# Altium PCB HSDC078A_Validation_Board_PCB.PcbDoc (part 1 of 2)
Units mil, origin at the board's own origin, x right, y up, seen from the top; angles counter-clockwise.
Board outline 3100 x 3100 mil, 4 copper layers (L1-TOP, L2, L3, L4-BOT), stack 61.6 mil thick; 80 components, 31 nets, 179 pads, 275 vias.
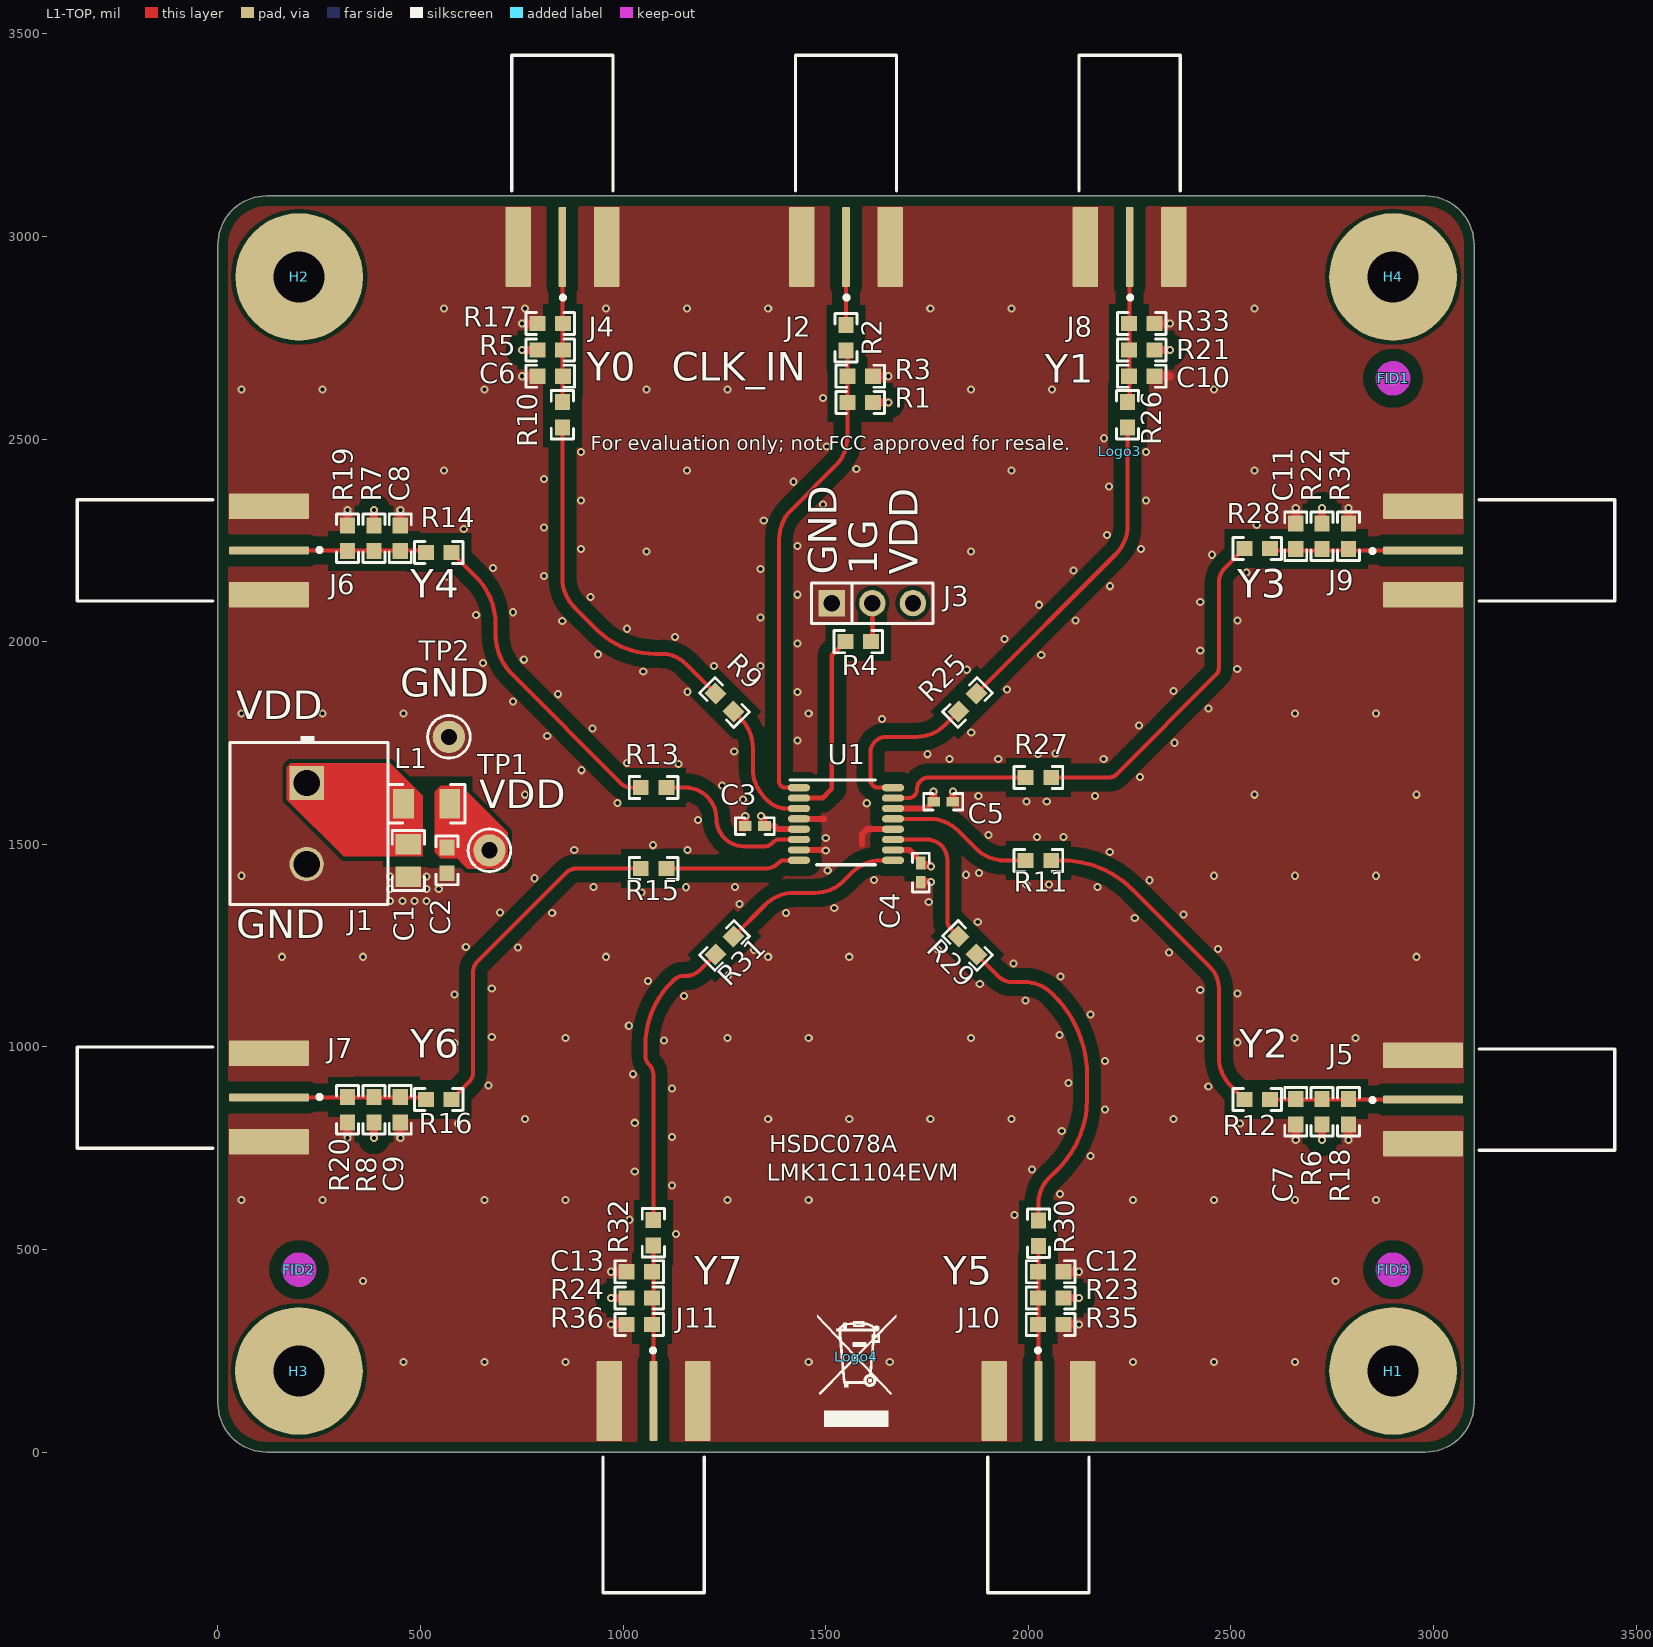
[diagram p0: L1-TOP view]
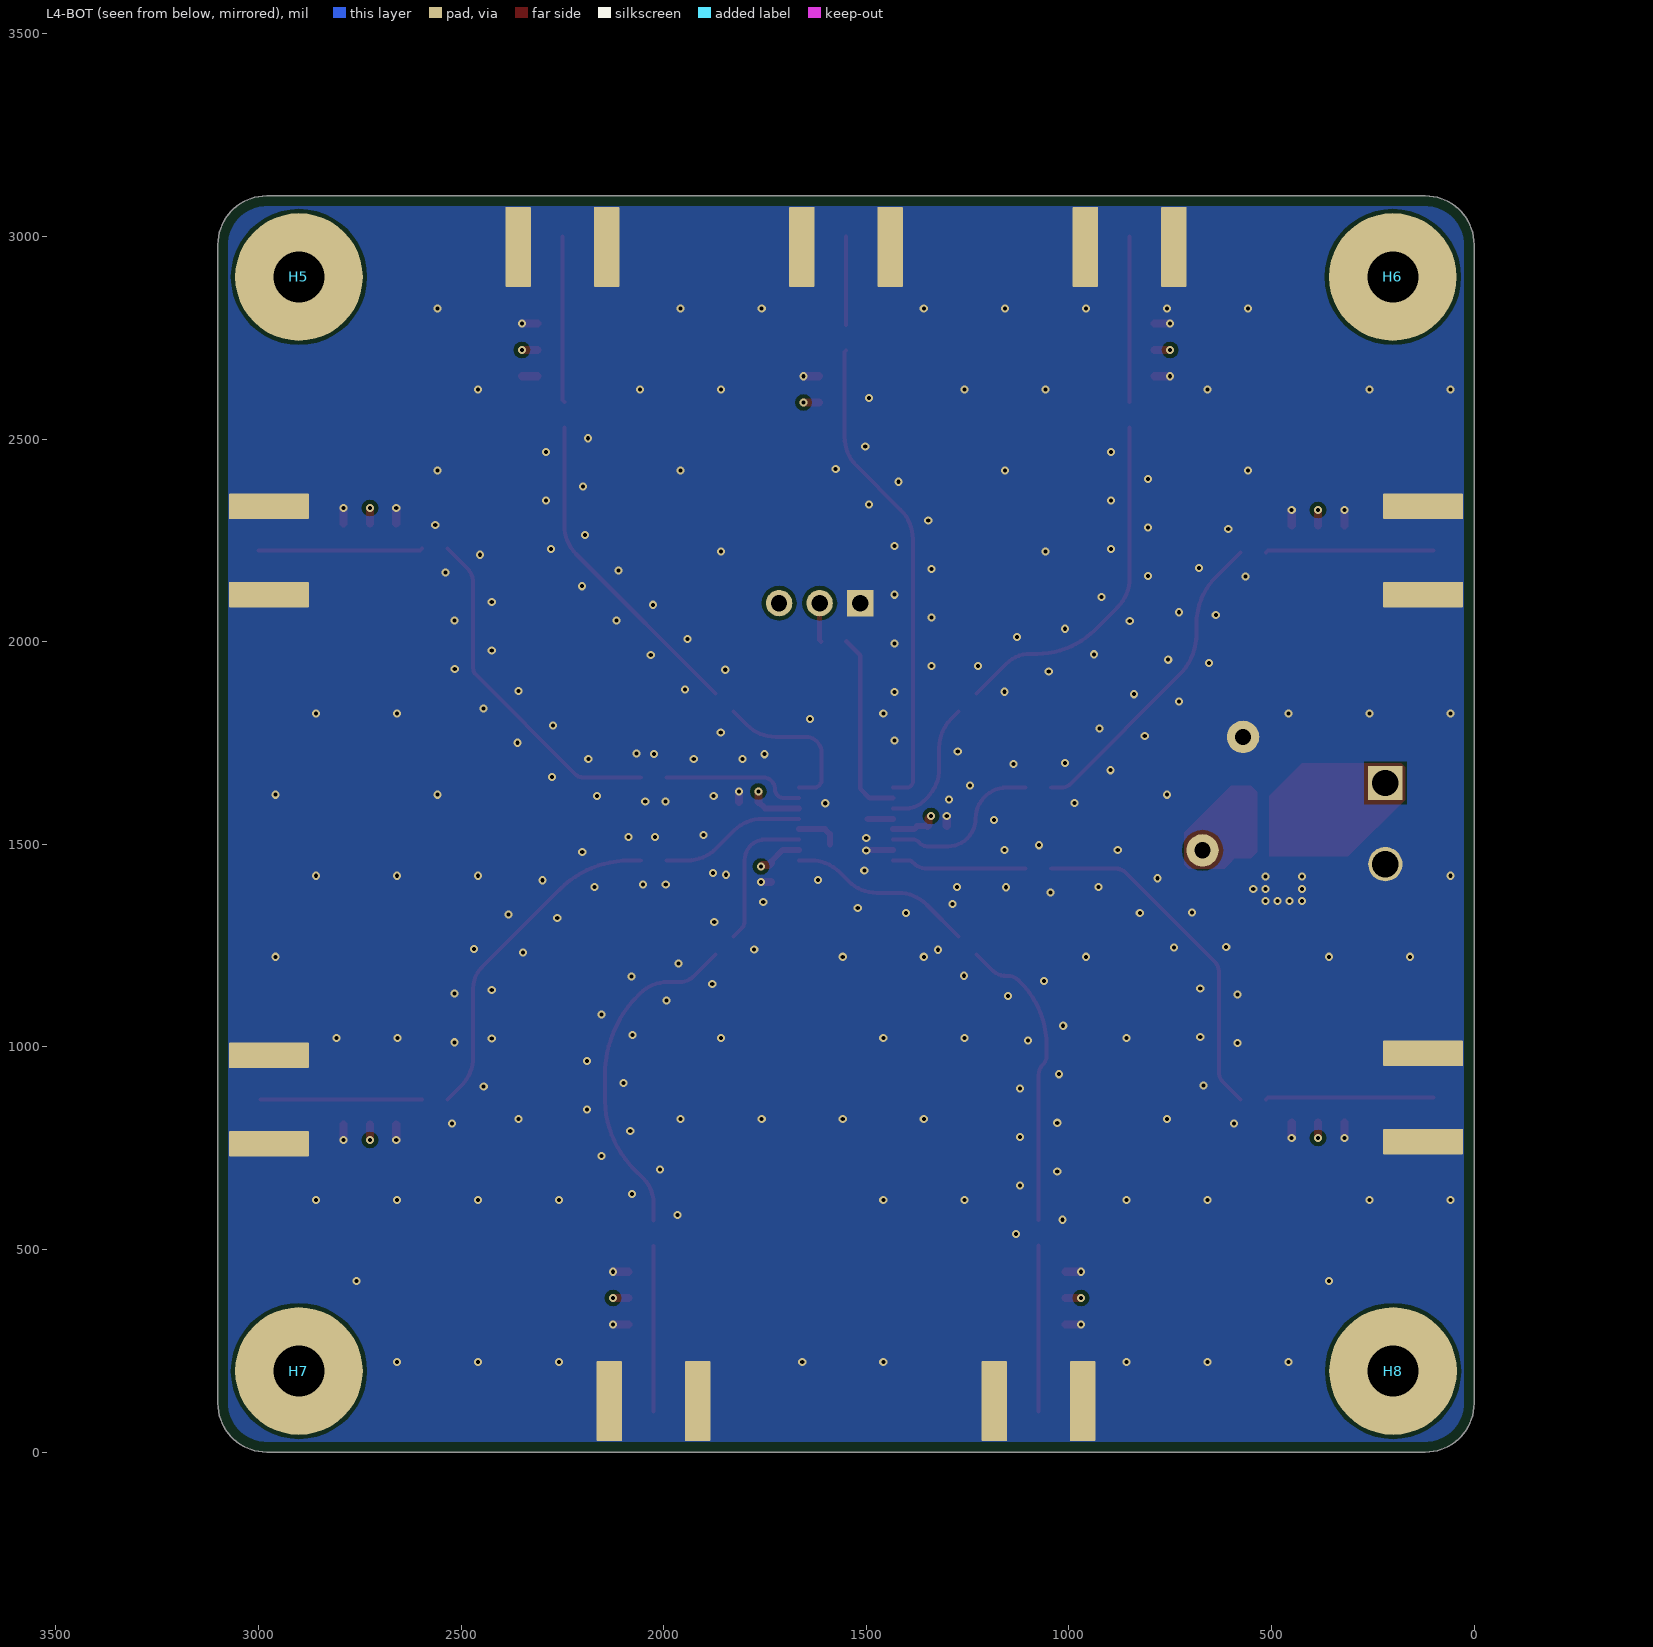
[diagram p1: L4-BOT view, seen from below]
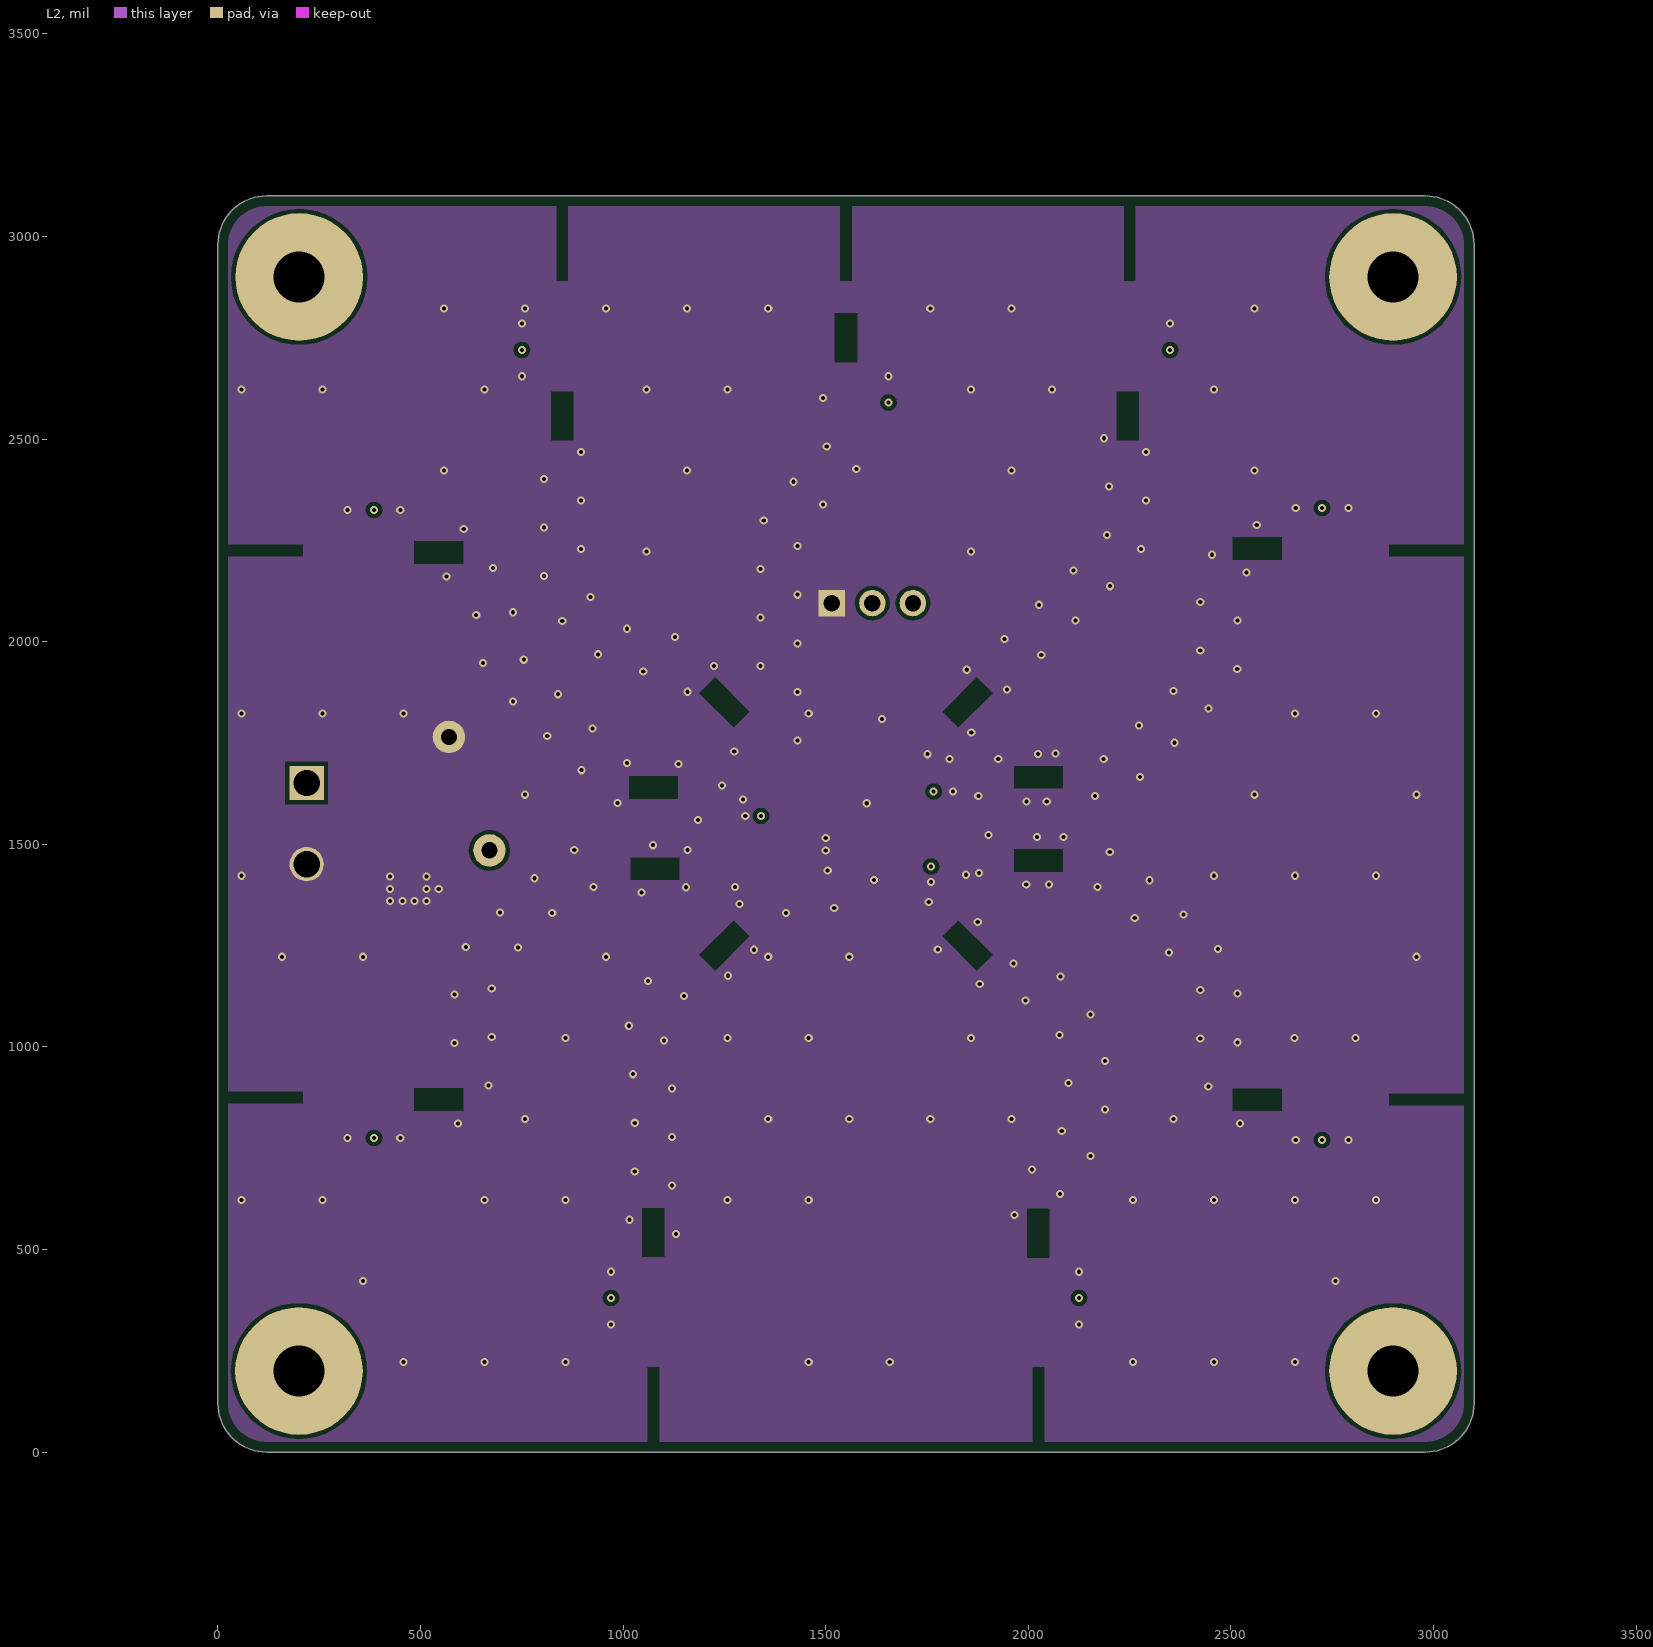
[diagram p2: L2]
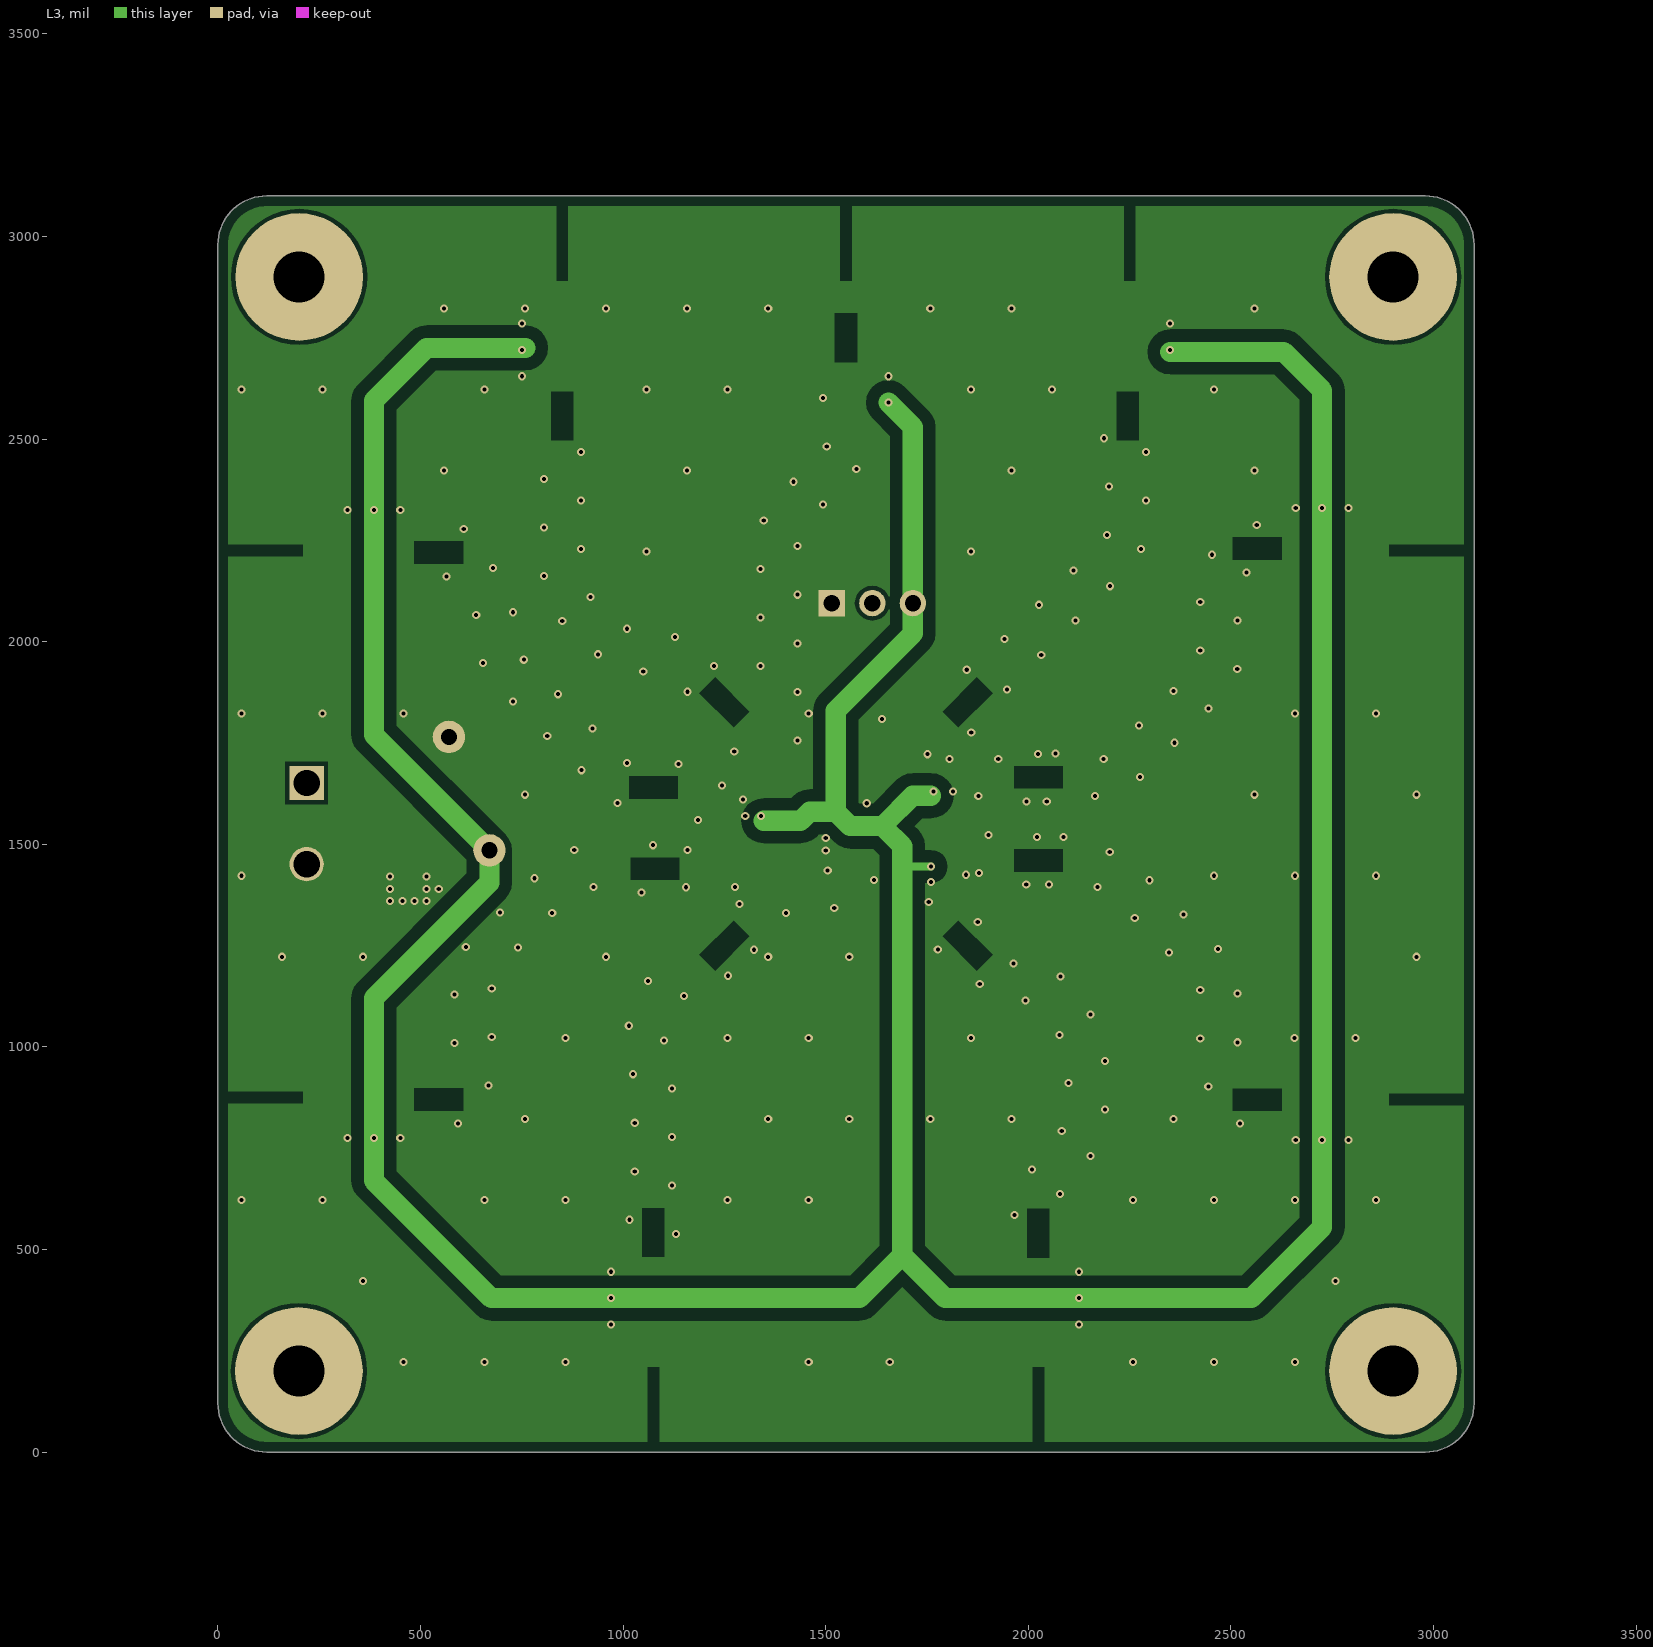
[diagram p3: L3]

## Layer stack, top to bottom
Top Solder: solder mask 0.4, Solder Resist, Dk 3.5
L1-TOP: signal copper 1.4
Dielectric 1: prepreg 6, FR-4 High TG, Dk 4.2
L2: signal copper 1.4
Dielectric 2: core 44, FR-4 High TG, Dk 4.2
L3: signal copper 1.4
Dielectric 3: prepreg 6, FR-4 High TG, Dk 4.2
L4-BOT: signal copper 1.4
Bottom Solder: solder mask 0.4, Solder Resist, Dk 3.5

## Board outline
120,0 cw(c120,120) 0,120 0,2980 cw(c120,2980) 120,3100 2980,3100 cw(c2980,2980) 3100,2980 3100,120 cw(c2980,120) 2980,0

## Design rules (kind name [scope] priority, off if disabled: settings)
AcuteAngle [All] p1: minimum=4.50000000000000E+0001 checktracksonly=FALSE
AssemblyTestPointUsage [All] p1: valid=2
BoardOutlineClearance BoardOutlineClearance_MountingHoles [OnCopper and InComponentClass('Mounting Holes')] p1: gap=39.37 ignorepadtopadclearanceinfootprint=FALSE
BoardOutlineClearance BoardOutlineClearance_Poly [OnCopper and IsPoly] p2: gap=25 ignorepadtopadclearanceinfootprint=FALSE
BoardOutlineClearance [OnCopper and Not InComponentClass('Logo') and not InComponentClass('FiducialMark') and not InRegion(1000,500,4000,800) and not InPoly] p3: gap=-1 ignorepadtopadclearanceinfootprint=FALSE
Clearance Clearance_Poly [InPolygon] p1: gap=10 ignorepadtopadclearanceinfootprint=TRUE except(30: Arc-Poly Track-Poly SMDPad-Poly)
Clearance Clearance_Keepouts [((IsTrack Or IsArc) And Not InPoly) And IsFree and IsKeepOut vs ((IsTrack Or IsArc) And Not InPoly) And IsFree and IsKeepOut] p2: gap=0 ignorepadtopadclearanceinfootprint=FALSE
Clearance Clearance_FiducialMark [IsKeepOut and InComponentClass('FiducialMark') vs IsPad and InComponentClass('FiducialMark')] p3: gap=0 ignorepadtopadclearanceinfootprint=FALSE
Clearance [All] p4: gap=7.87 ignorepadtopadclearanceinfootprint=TRUE
ComponentClearance ComponentClearance_MountingHoles_FiducialMarks [InComponentClass('Mounting Holes') vs InComponentClass('FiducialMark')] p1: gap=50 collisioncheckmode=3 verticalgap=10 showdistances=FALSE
ComponentClearance ComponentClearance_Shunt [InComponentClass('Header') vs InComponentClass('Shunt')] p2: gap=0 collisioncheckmode=3 verticalgap=0 showdistances=FALSE
ComponentClearance ComponentClearance_Logo [InComponentClass('Logo')] p3: gap=50 collisioncheckmode=3 verticalgap=10 showdistances=FALSE
ComponentClearance ComponentClearance_ScrewToNut [(HasFootprint('NY PMS 440 0025 PH')) vs (HasFootprint('Keystone_1902C'))] p4: gap=5 collisioncheckmode=3 verticalgap=10 showdistances=FALSE
ComponentClearance ComponentClearance_MountingHoles [InComponentClass('Mounting Holes')] p5: gap=100 collisioncheckmode=3 verticalgap=100000 showdistances=FALSE
ComponentClearance ComponentClearance_SmallPassives [HasFootprint('0201*') or HasFootprint('0402*') or HasFootprint('0508') or HasFootprint('0603*') or HasFootprint('0612') or HasFootprint('0805*') or HasFootprint('0815*') or HasFootprint('0830*') or HasFootprint('1206*') or HasFootprint('1210*') or HasFootprint('1808*') or HasFootprint('1812*') or HasFootprint('1825*') or HasFootprint('2010*') or HasFootprint('2220*') or HasFootprint('2225*') or HasFootprint('2512*') or HasFootprint('2728*') or HasFootprint('3518*') vs HasFootprint('0201*') or HasFootprint('0402*') or HasFootprint('0508') or HasFootprint('0603*') or HasFootprint('0612') or HasFootprint('0805*') or HasFootprint('0815*') or HasFootprint('0830*') or HasFootprint('1206*') or HasFootprint('1210*') or HasFootprint('1808*') or HasFootprint('1812*') or HasFootprint('1825*') or HasFootprint('2010*') or HasFootprint('2220*') or HasFootprint('2225*') or HasFootprint('2512*') or HasFootprint('2728*') or HasFootprint('3518*')] p6: gap=14.96 collisioncheckmode=3 verticalgap=10 showdistances=FALSE
ComponentClearance ComponentClearance_THtoSMT [IsThruComponent vs IsSMTComponent] p7: gap=20 collisioncheckmode=3 verticalgap=30 showdistances=FALSE
ComponentClearance ComponentClearance_THtoTH [IsThruComponent vs IsThruComponent] p8: gap=30 collisioncheckmode=3 verticalgap=30 showdistances=FALSE
ComponentClearance [All] p9: gap=30 collisioncheckmode=3 verticalgap=10 showdistances=FALSE
DiffPairsRouting [All] p1: maxlimit=100 minlimit=10 mostfreqgap=10 toplayer_minwidth=15 toplayer_maxwidth=15 toplayer_prefwidth=15 midlayer1_minwidth=15 midlayer1_maxwidth=15 midlayer1_prefwidth=15 midlayer2_minwidth=15 midlayer2_maxwidth=15 midlayer2_prefwidth=15 bottomlayer_minwidth=15 bottomlayer_maxwidth=15 bottomlayer_prefwidth=15 maxuncoupledlength=1000
FabricationTestPointUsage TestPointUsage [All] p1: valid=2 allowmultiple=FALSE
FabricationTestpoint Testpoint [All] p1: side=3 testpointundercomponent=TRUE minsize=40 maxsize=100 preferedsize=60 minholesize=0 maxholesize=40 preferedholesize=32 testpointgrid=1 allowsidetop=TRUE allowsidebottom=TRUE usegrid=TRUE gridtolerance=0.01
FanoutControl Fanout_LCC [IsLCC] p1: bgadir=Out bgaviamode=Centered fanoutstyle=Auto fanoutdirection=Alternating viagrid=1 // Fanout_LCC (Default Rule)
FanoutControl Fanout_BGA [IsBGA] p2: bgadir=Out bgaviamode=Centered fanoutstyle=Auto fanoutdirection=Alternating viagrid=1 // Fanout_BGA (Default Rule)
FanoutControl Fanout_Default [All] p4: bgadir=Out bgaviamode=Centered fanoutstyle=Auto fanoutdirection=Alternating viagrid=1 // Fanout_Default (Default Rule)
FanoutControl Fanout_Small [(CompPinCount < 5)] p5: bgadir=Out bgaviamode=Centered fanoutstyle=Auto fanoutdirection=OutThenIn viagrid=1 // Fanout_Small (Default Rule)
HoleSize [All] p1: absolutevalues=TRUE maxlimit=251 minlimit=7.87 maxpercent=80.000 minpercent=20.000
MinimumAnnularRing MinimumAnnularRing_ThermalPadVias [IsVia and InAnyComponent] p1: minimumring=5.91
MinimumAnnularRing [All] p2: minimumring=4.9
MinimumSolderMaskSliver MinimumSolderMaskSliver_Logo [InComponentClass('Logo') vs InComponentClass('Logo')] p1: minsoldermaskwidth=0.7
MinimumSolderMaskSliver [All] p2: minsoldermaskwidth=3.94
PlaneConnect [All] p1: planeconnectstyle=Relief reliefexpansion=10 reliefentries=4 reliefconductorwidth=10 reliefairgap=10
PolygonConnect [All] p1: connectstyle=Direct reliefconductorwidth=10 reliefentries=4 polygonreliefangle="90 Angle" airgapwidth=10
RoutingVias ThermalPadVias [IsVia and InAnyComponent] p1: holewidth=7.87 width=19.68 viastyle="Through Hole" minholewidth=7.87 minwidth=19.68 maxholewidth=12.99 maxwidth=23.62
RoutingVias [All] p2: holewidth=10 width=20 viastyle="Through Hole" minholewidth=8 minwidth=19 maxholewidth=40 maxwidth=40
SilkToBoardRegionClearance [Not ((IsComment or IsDesignator) And (Hide <> 'False')) and not InRegion(1000,500,4000,800)] p1:
SilkToSilkClearance SilkToSilkClearance_Pb-FreeLogo [(HasFootprint('Pb-Free_Overlay_Medium') OR HasFootprint('Pb-Free_Overlay_Small')) vs (HasFootprint('Pb-Free_Overlay_Medium') OR HasFootprint('Pb-Free_Overlay_Small'))] p1: silktosilkclearance=0
SilkToSilkClearance [All] p2: silktosilkclearance=3.94
SilkToSolderMaskClearance SilkToComponentPadClearance [(IsPad or IsFill or IsRegion) and InAnycomponent] p1: minsilkscreentomaskgap=5 clearancetoexposedcopper=TRUE
SilkToSolderMaskClearance "Silk to Solder Mask Opening" [All] p2: minsilkscreentomaskgap=3.94 clearancetoexposedcopper=FALSE
SolderMaskExpansion [All] p1: expansion=1.97
Width [All] p1: maxlimit=100 minlimit=6 preferedwidth=10 checkconnectedcopper=TRUE
15 further rules are at their usual default settings.

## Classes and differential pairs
component class "Mounting Holes": H1 H2 H3 H4
component class HSDC078E1_Hardware: !PCB FID1 FID2 FID3 H1 H2 H3 H4 H5 H6 H7 H8 Logo1 Logo2 Logo3 Logo4 ZZ1 ZZ2 ZZ3
component class FiducialMark: FID1 FID2 FID3
component class AssemblyNote: ZZ1 ZZ2 ZZ3
component class Header: J3
component class HSDC078E1_Validation_Board_Schematic: C1 C2 C3 C4 C5 C6 C7 C8 C9 C10 C11 C12 C13 J1 J2 J3 J4 J5 J6 J7 J8 J9 J10 J11 L1 R1 R2 R3 R4 R5 R6 R7 R8 R9 R10 R11 R12 R13 R14 R15 R16 R17 R18 R19 R20 R21 R22 R23 R24 R25 R26 R27 R28 R29 R30 R31 R32 R33 R34 R35 R36 TP1 TP2 U1

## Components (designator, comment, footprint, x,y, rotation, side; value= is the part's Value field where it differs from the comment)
C1 "C0805C106K8PACTU" 0805_HV 470,1460 r270 top value=10uF
C2 "C0603X105J8RAC7867" 0603 565,1460 r270 top value=1uF
C3 "C0402C104K8RACAUTO" 0402 1325,1545 r0 top value=0.1uF
C4 "C0402C104K8RACAUTO" 0402 1735,1430 r90 top value=0.1uF
C5 "C0402C104K8RACAUTO" 0402 1790,1605 r180 top value=0.1uF
C6 "GRM1885C2A5R0CA01D" 0603 820,2655 r180 top value=5pF
C7 "GRM1885C2A5R0CA01D" 0603 2660,840 r270 top value=5pF
C8 "GRM1885C2A5R0CA01D" 0603 450,2255 r90 top value=5pF
C9 "GRM1885C2A5R0CA01D" 0603 450,845 r270 top value=5pF
C10 "GRM1885C2A5R0CA01D" 0603 2280,2655 r0 top value=5pF
C11 "GRM1885C2A5R0CA01D" 0603 2660,2260 r90 top value=5pF
C12 "GRM1885C2A5R0CA01D" 0603 2055,445 r0 top value=5pF
C13 "GRM1885C2A5R0CA01D" 0603 1040,445 r180 top value=5pF
FID1 "Fiducial" Fiducial10-20 2900,2650 r0 top
FID2 "Fiducial" Fiducial10-20 200,450 r180 top
FID3 "Fiducial" Fiducial10-20 2900,450 r0 top
H1 "NY PMS 440 0025 PH" "NY PMS 440 0025 PH" 2900,200 r0 top
H2 "NY PMS 440 0025 PH" "NY PMS 440 0025 PH" 200.53,2900 r0 top
H3 "NY PMS 440 0025 PH" "NY PMS 440 0025 PH" 200,200 r0 top
H4 "NY PMS 440 0025 PH" "NY PMS 440 0025 PH" 2900,2900 r0 top
H5 "1902C" Keystone_1902C 2900,2900 r180 bottom
H6 "1902C" Keystone_1902C 200.53,2900 r180 bottom
H7 "1902C" Keystone_1902C 2900,200 r180 bottom
H8 "1902C" Keystone_1902C 200,200 r180 bottom
J1 "039544-3002" Molex_039544-3002 219,1551 r270 top
J2 "CON-SMA-EDGE-S" FP-SMA-EDGE-S-CUSTOM 1550,3260 r0 top
J3 "PBC03SAAN" PBC03SAAN 1615,2095 r0 top
J4 "CON-SMA-EDGE-S" FP-SMA-EDGE-S-CUSTOM 850,3260 r0 top
J5 "CON-SMA-EDGE-S" FP-SMA-EDGE-S-CUSTOM 3260,870 r270 top
J6 "CON-SMA-EDGE-S" FP-SMA-EDGE-S-CUSTOM -160,2225 r90 top
J7 "CON-SMA-EDGE-S" FP-SMA-EDGE-S-CUSTOM -160,875 r90 top
J8 "CON-SMA-EDGE-S" FP-SMA-EDGE-S-CUSTOM 2250,3260 r0 top
J9 "CON-SMA-EDGE-S" FP-SMA-EDGE-S-CUSTOM 3260,2225 r270 top
J10 "CON-SMA-EDGE-S" FP-SMA-EDGE-S-CUSTOM 2025,-160 r180 top
J11 "CON-SMA-EDGE-S" FP-SMA-EDGE-S-CUSTOM 1075,-160 r180 top
L1 "BLM31SN500SZ1L" 1206 515,1600 r0 top value="50 ohm"
Logo3 "FCC disclaimer" FCC_disclaimer 2225,2470 r0 top
Logo4 "WEEE logo" WEEE_Minimum 1575,235 r0 top
R1 "CRCW0603100RFKEA" 0603 1585,2590 r180 top value=100
R2 "RC0603JR-070RL" 0603 1550,2750 r270 top value=0
R3 "CRCW0603100RFKEA" 0603 1585,2655 r0 top value=100
R4 "RC0603JR-070RL" 0603 1580,2000 r0 top value=0
R5 "CRCW0603100RFKEA" 0603 820,2720 r180 top value=100
R6 "CRCW0603100RFKEA" 0603 2725,840 r270 top value=100
R7 "CRCW0603100RFKEA" 0603 385,2255 r90 top value=100
R8 "CRCW0603100RFKEA" 0603 385,845 r270 top value=100
R9 "RC0603JR-070RL" 0603 1250,1850 r135 top value=0
R10 "RC0603JR-070RL" 0603 850,2560 r90 top value=0
R11 "RC0603JR-070RL" 0603 2025,1460 r0 top value=0
R12 "RC0603JR-070RL" 0603 2565,870 r0 top value=0
R13 "RC0603JR-070RL" 0603 1075,1640 r180 top value=0
R14 "RC0603JR-070RL" 0603 545,2220 r180 top value=0
R15 "RC0603JR-070RL" 0603 1075,1440 r180 top value=0
R16 "RC0603JR-070RL" 0603 545,870 r180 top value=0
R17 "CRCW0603100RFKEA" 0603 820,2785 r180 top value=100
R18 "CRCW0603100RFKEA" 0603 2790,840 r270 top value=100
R19 "CRCW0603100RFKEA" 0603 320,2255 r90 top value=100
R20 "CRCW0603100RFKEA" 0603 320,845 r270 top value=100
R21 "CRCW0603100RFKEA" 0603 2280,2720 r0 top value=100
R22 "CRCW0603100RFKEA" 0603 2725,2260 r90 top value=100
R23 "CRCW0603100RFKEA" 0603 2055,380 r0 top value=100
R24 "CRCW0603100RFKEA" 0603 1040,380 r180 top value=100
R25 "RC0603JR-070RL" 0603 1850,1850 r45 top value=0
R26 "RC0603JR-070RL" 0603 2245,2560 r90 top value=0
R27 "RC0603JR-070RL" 0603 2025,1665 r0 top value=0
R28 "RC0603JR-070RL" 0603 2565,2230 r0 top value=0
R29 "RC0603JR-070RL" 0603 1850,1250 r315 top value=0
R30 "RC0603JR-070RL" 0603 2025,540 r270 top value=0
R31 "RC0603JR-070RL" 0603 1250,1250 r225 top value=0
R32 "RC0603JR-070RL" 0603 1074.45,541.5 r270 top value=0
R33 "CRCW0603100RFKEA" 0603 2280,2785 r0 top value=100
R34 "CRCW0603100RFKEA" 0603 2790,2260 r90 top value=100
R35 "CRCW0603100RFKEA" 0603 2055,315 r0 top value=100
R36 "CRCW0603100RFKEA" 0603 1040,315 r180 top value=100
TP1 "5000" Keystone5000 670,1485 r180 top
TP2 "5001" Keystone5001 570,1765 r90 top
U1 "LMK1C1108PW" PW0016A_N 1550,1550 r0 top
ZZ1 "These assemblies are ESD sensitive, ESD precautions shall be observed." AssemblyNote 200,4600 r0 top
ZZ2 "These assemblies must be clean and free from flux and all contaminants. Use of no clean flux is not acceptable." AssemblyNote 200,4500 r0 top
ZZ3 "These assemblies must comply with workmanship standards IPC-A-610 Class 2, unless otherwise specified." AssemblyNote 200,4400 r0 top

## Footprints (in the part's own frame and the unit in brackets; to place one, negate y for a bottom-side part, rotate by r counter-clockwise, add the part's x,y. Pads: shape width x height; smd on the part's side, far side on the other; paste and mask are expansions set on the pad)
0402 [mm] "0402 from SM-752 data"
  rect 0.8x0.6 smd: 1(-0.6,0) 2(0.6,0)
  silkscreen extent -1.22,-0.52 1.22,0.52, body extent -0.55,-0.3 0.55,0.3, height 0.6
0603 [mm] "0603 from SM-752 data"
  rect 1x0.95 smd: 1(-0.8,0) 2(0.8,0)
  silkscreen extent -1.52,-0.69 1.52,0.69, body extent -0.87,-0.47 0.87,0.47, height 1
0805_HV [mil] "0805 with 30mil clearance between pads"
  rect 50x63 smd: 1(-40,0) 2(40,0)
  silkscreen extent -74,-40 74,40, body extent -43,-29 43,29, height 57
1206 [mm] "1206 from SM-752 data"
  rect 1.3x1.85 smd: 1(-1.45,0) 2(1.45,0)
  silkscreen extent -2.4,-1.21 2.4,1.21, body extent -1.7,-0.9 1.7,0.9, height 1.35
AssemblyNote [mil] "Assembly Note"
FCC_disclaimer [mil]
Fiducial10-20 [mm]
  round 1 smd mask+0.5: 1(0,0)
  L1-TOP keep-out circle w1.178: c0,0 r0.5
FP-SMA-EDGE-S-CUSTOM [mm]
  rrect21% 0.483x5 smd paste+0 mask+0: 1(0,-7.26)
  rrect6% 1.6x5 smd paste+0 mask+0: 2(-2.77,-7.26) 3(2.77,-7.26)
  rrect6% 1.6x5 smd far side paste+0 mask+0: 4(-2.77,-7.26) 5(2.77,-7.26)
  silkscreen extent -3.17,-10.56 3.17,4.76, body extent -3.87,-10.05 3.87,5.05, height 0.25
Keystone5000 [mil] "For Keystone 500x miniature loop terminals"
  round 80 hole 40: 1(0,0)
  silkscreen extent -52,-52 52,52, body extent -49,-49 49,49, height 182
Keystone5001 [mil] "For Keystone 500x miniature loop terminals"
  round 80 hole 40: 1(0,0)
  silkscreen extent -52,-52 52,52, body extent -49,-49 49,49, height 182
Keystone_1902C [mil] "Hex Standoff, 4-40 threaded, nylon"
  round 1 on Mech4: 0(0,0)
  body extent -145,-126 146,126, height 501
Molex_039544-3002 [mm] "Terminal Block, 5.08mm, 2x1, TH"
  rect 2.15x2.15 hole 1.65: 1(-2.54,0)
  round 2.15 hole 1.65: 2(2.54,0)
  silkscreen extent -5.5,-4.8 5.08,5.11, body extent -5.08,-4.8 5.08,5.11, height 14.48
"NY PMS 440 0025 PH" [mm] "4-40 nylon screw and mounting hole"
  round 8 hole 3.2: 1(0,0)
  body extent -3.3,-3.3 3.3,3.3, height 2.69
PBC03SAAN [mm] "Sullins 100mil, 1x3, 230 mil above insulator"
  rect 1.65x1.65 hole 1.016: 1(-2.54,0)
  round 1.65 hole 1.016: 2(0,0) 3(2.54,0)
  silkscreen extent -3.81,-1.27 3.81,1.27, body extent -3.81,-1.27 3.81,1.27, height 8.38
PW0016A_N [mm] "TSOP, 16-Leads, Body 5x4.4mm, Pitch 0.65mm, IPC Medium Density"
  oval 1.4x0.45 smd: 1(-2.95,2.275) 2(-2.95,1.625) 3(-2.95,0.975) 4(-2.95,0.325) 5(-2.95,-0.325) 6(-2.95,-0.975) 7(-2.95,-1.625) 8(-2.95,-2.275) 9(2.95,-2.275) 10(2.95,-1.625) 11(2.95,-0.975) 12(2.95,-0.325) 13(2.95,0.325) 14(2.95,0.975) 15(2.95,1.625) 16(2.95,2.275)
  silkscreen extent -3.5,-2.55 1.85,2.75, body extent -3.21,-2.5 3.21,2.5, height 1
WEEE_Minimum [mil] "WEEElie bin"
  silkscreen extent -95,-172 99,104

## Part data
C1: library part CMP-0007732-1, "CAP, CERM, 10 uF, 10 V, +/- 10%, X5R, 0805", Cap_Case=0805, Manufacturer=Kemet, Supplier Part Number 1=399-4925-1-ND, TempCo=X5R, Tolerance_%=10%, Value1="0.003 ohm", Value2=10V, ValueDisplayed=10uF
C2: library part CMP-0084112-1, "CAP, CERM, 1 µF, 10 V,+/- 5%, X7R, AEC-Q200 Grade 1, 0603", Cap_Case=0603, Manufacturer=Kemet, TempCo=X7R, Tolerance_%=5%, Value2=10V, ValueDisplayed=1µF
C3 C4 C5: library part CMP-0079150-1, "CAP, CERM, 0.1 µF, 10 V,+/- 10%, X7R, AEC-Q200 Grade 1, 0402", Cap_Case=0402, Manufacturer=Kemet, Supplier Part Number 1=399-15984-1-ND, TempCo=X7R, Tolerance_%=10%, Value2=10V, ValueDisplayed=0.1µF
C6 C7 C8 C9 C10 C11 C12 C13: library part CMP-0007277-4, "CAP, CERM, 5 pF, 100 V, +/- 5%, C0G/NP0, 0603", Cap_Case=0603, Manufacturer=MuRata, Supplier Part Number 1=490-6393-1-ND, TempCo=C0G/NP0, Tolerance_%=5%, Value1=Unknown, Value2=100V, ValueDisplayed=5pF
FID1 FID2 FID3: library part CMP-0077181-1, "Fiducial mark.  There is nothing to buy or mount.", Manufacturer=N/A
H1 H2 H3 H4: library part CMP-0003617-1, "Machine Screw, Round, #4-40 x 1/4, Nylon, Philips panhead", Manufacturer="B&F Fastener Supply", Supplier Part Number 1=H542-ND
H5 H6 H7 H8: library part CMP-0003610-1, "Standoff, Hex, 0.5\"L #4-40 Nylon", Manufacturer=Keystone, Supplier Part Number 1=36-1902C-ND
J1: library part CMP-0055345-1, "Terminal Block, 5.08mm, 2x1, TH", Color=Black, Current_A=15A, Manufacturer=Molex, Supplier Part Number 1=WM7853-ND, Voltage_V=300V
J2 J4 J5 J6 J7 J8 J9 J10 J11: library part CMP-0088000-4, "CONN SMA JACK STR EDGE MNT", Manufacturer="RF Solutions Ltd."
J3: library part CMP-0002334-1, "Header, 100mil, 3x1, Gold, TH", Manufacturer="Sullins Connector Solutions", Supplier Part Number 1=S1011E-03-ND
L1: library part CMP-0003368-1, "Ferrite Bead, 50 ohm @ 100 MHz, 12 A, 1206", Manufacturer=MuRata, Supplier Part Number 1=490-13270-1-ND, Value1="0.0016 ohm", Value2=12A, ValueDisplayed="50 ohm"
Logo3: library part CMP-0074847-1, "FCC_disclaimer"
Logo4: library part CMP-0074769-1
R1 R3 R5 R6 R7 R8 R17 R18 R19 R20 R21 R22 R23 R24 R33 R34 R35 R36: library part CMP-0021991-4, "RES, 100, 1%, 0.1 W, AEC-Q200 Grade 0, 0603", Manufacturer=Vishay-Dale, Power_W=100mW, Supplier Part Number 1=541-100HCT-ND, TempCo="100 ppm/C", Tolerance_%=1%, Value2=0.1W, Value_Code=100R, ValueDisplayed=100
R2 R4 R9 R10 R11 R12 R13 R14 R15 R16 R25 R26 R27 R28 R29 R30 R31 R32: library part CMP-0025885-5, "RES, 0, 5%, 0.1 W, 0603", Manufacturer=Yageo, Power_W=100mW, Supplier Part Number 1=311-0.0GRCT-ND, TempCo="200 ppm/C", Tolerance_%=5%, Value2=0.1W, Value_Code=0000, ValueDisplayed=0
TP1: library part CMP-0055137-1, "Test Point, Miniature, Red, TH", Color=Red, Manufacturer=Keystone, Supplier Part Number 1=36-5000-ND
TP2: library part CMP-0055138-1, "Test Point, Miniature, Black, TH", Color=Black, Manufacturer=Keystone, Supplier Part Number 1=36-5001-ND
U1: library part CMP-0860875-1, "3.3-V and 2.5-V LVCMOS High-Performance Clock Buffer Family, PW0016A (TSSOP-16)", Alternate Manufacturer="Texas Instruments"
ZZ1: library part CMP-0077236-1
ZZ2: library part CMP-0077237-1
ZZ3: library part CMP-0077238-1

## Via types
v1: diameter 20, hole 10, L1-TOP to L4-BOT, tented both sides, 275 vias

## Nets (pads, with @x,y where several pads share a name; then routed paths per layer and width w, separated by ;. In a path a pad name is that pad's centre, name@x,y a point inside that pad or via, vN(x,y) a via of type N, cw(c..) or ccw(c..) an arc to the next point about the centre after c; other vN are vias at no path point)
1G: R4.1 U1.2 | length 467.5
  L1-TOP w12: U1.2@1433.86,1613.98 1491.93,1613.98 1515,1637.05 1515,1966.5 R4.1@1548.5,2000
CLKIN: R1.2 R2.2 R3.1 U1.1 | length 1183.8
  L1-TOP w10: U1.1@1433.86,1639.57 1400.43,1639.57 cw(c1400.43,1655) 1385,1655 1385,2253.58 cw(c1485,2253.58) 1414.29,2324.29 1524.21,2434.21 ccw(c1453.5,2504.93) 1553.5,2504.93 R1.2@1553.5,2590 1553.5,2715 R2.2@1550,2718.5
GND: C1.2 C2.2 C3.1 C4.1 C5.1 C6.2 C7.2 C8.2 C9.2 C10.2 C11.2 C12.2 C13.2 J1.2 J2.2 J2.3 J2.4 J2.5 J3.1 J4.2 J4.3 J4.4 J4.5 J5.2 J5.3 J5.4 J5.5 J6.2 J6.3 J6.4 J6.5 J7.2 J7.3 J7.4 J7.5 J8.2 J8.3 J8.4 J8.5 J9.2 J9.3 J9.4 J9.5 J10.2 J10.3 J10.4 J10.5 J11.2 J11.3 J11.4 J11.5 R3.2 R17.2 R18.2 R19.2 R20.2 R33.2 R34.2 R35.2 R36.2 TP2.1 U1.4 U1.7 U1.12 | length 965.7
  L1-TOP w15: U1.7@1433.86,1486.02 1498.98,1486.02 v1(1500,1485) ; U1.4@1433.86,1562.8 1497.2,1562.8 ; 1590,1500 1590,1525 1602.2,1537.2 U1.12@1666.14,1537.2
  L1-TOP w20: v1(320,775) R20.2@320,813.5 ; R19.2@320,2286.5 v1(320,2325) ; v1(450,775) C9.2@450,813.5 ; C8.2@450,2286.5 v1(450,2325) ; v1(750,2655) C6.2@788.5,2655 ; v1(750,2785) R17.2@788.5,2785 ; v1(970,315) R36.2@1008.5,315 ; v1(970,445) C13.2@1008.5,445 ; C3.1@1301.38,1545 v1(1301.38,1570) ; R3.2@1616.5,2655 v1(1655,2655) ; C4.1@1735,1406.38 v1(1760,1406.38) ; C5.1@1813.62,1605 v1(1813.62,1630) ; R35.2@2086.5,315 v1(2125,315) ; C12.2@2086.5,445 v1(2125,445) ; C10.2@2311.5,2655 2350,2655 ; R33.2@2311.5,2785 v1(2350,2785) ; v1(2660,770) C7.2@2660,808.5 ; C11.2@2660,2291.5 v1(2660,2330) ; v1(2790,770) R18.2@2790,808.5 ; R34.2@2790,2291.5 v1(2790,2330)
  other v1: 458,222.3 658,222.3 858,222.3 1458,222.3 1658,222.3 2258,222.3 2458,222.3 2658,222.3 358,422.3 2758,422.3 1130.02,537.78 1015.4,573.34 1965.95,585.24 58,622.3 258,622.3 658,622.3 858,622.3 1258,622.3 1458,622.3 2258,622.3 2458,622.3 2658,622.3 2858,622.3 2077.83,637.35 1120.21,657.38 1028.69,692.6 2009.03,697.25 2153.58,730.42 1120.21,777.38 2082.49,792.13 592.66,810.95 2521.97,810.95 1028.69,812.6 758,822.3 1358,822.3 1558,822.3 1758,822.3 1958,822.3 2358,822.3 2189.27,844.99 1120.21,897.38 2444.08,902.24 667.96,904.38 2099.24,910.95 1024.72,932.53 2188.77,964.99 584.24,1009.55 2515.76,1011.29 1101.22,1015.87 2424.24,1020.59 2656.97,1021.58 2806.95,1021.58 858,1022.3 1258,1022.3 1458,1022.3 1858,1022.3 675.76,1024.13 2077.31,1028.93 1013.94,1052.05 2153.67,1079.74 1992.8,1114.12 1149.99,1125.51 584.24,1129.55 2515.76,1131.29 2424.24,1140.59 675.76,1144.13 1880.06,1155.23 1061.55,1162.2 2079.18,1173.83 1259.06,1175.55 1963.51,1205.76 158,1222.3 358,1222.3 958,1222.3 1358,1222.3 1558,1222.3 2958,1222.3 2347.47,1232.82 1323.22,1239.72 1776.51,1239.98 2468.23,1241.48 740.12,1245.41 611.66,1246.38 1875.09,1308.42 2262.62,1317.67 2383.38,1326.33 824.97,1330.26 1401.6,1330.58 696.52,1331.23 1521.02,1342.41 1287.43,1352.14 1754.24,1357.9 425,1360 455,1360 485,1360 515,1360 1045.76,1380.95 425,1390 515,1390 545,1390 926.49,1394.24 1155.6,1393.94 1275.6,1394.24 2170.57,1394.66 1994.78,1400.95 2050.73,1400.95 1619.05,1411.62 2298.52,1411.19 781.37,1416.08 425,1420 515,1420 58,1422.3 2458,1422.3 2658,1422.3 2858,1422.3 1845.76,1424.78 1878.08,1428.93 1504.86,1435.62 2200.85,1480.89 879.32,1485.41 1158.9,1485.76 1073.63,1497.67 1500,1515 2086.62,1517.67 2021.39,1517.97 1901.5,1523.21 1184.51,1559.9 986.12,1601.78 1601.2,1601.17 1995.75,1605.95 2045.45,1605.95 1295.96,1610.67 1876.49,1619.24 2164.71,1619.24 758,1622.3 2558,1622.3 2958,1622.3 1244.33,1644.76 2275.37,1665.66 897.55,1682.74 1136.62,1697.67 1009.1,1700.61 1805.71,1710.76 1925.71,1710.76 2186.03,1710.76 1751.55,1722.24 2023.63,1722.67 2066.76,1724.05 1274.24,1728.68 2360.22,1750.51 1430.76,1755.85 812.69,1767.59 1859.06,1775.55 924.25,1785.47 2273.35,1793.06 1638.53,1809.57 58,1822.3 258,1822.3 458,1822.3 1458,1822.3 2658,1822.3 2858,1822.3 2445.08,1835.37 727.84,1852.45 839.39,1870.32 1158.89,1876.4 1430.76,1875.85 2358.21,1877.92 1947.01,1882.3 1049.64,1926.03 1848.06,1930.72 2515.53,1932.51 1339.24,1939.68 1224.6,1940.11 654.22,1947.21 754.82,1955.45 2031.86,1967.15 937.53,1968.83 2424.24,1978.11 1430.76,1995.85 1941.41,2006.12 1127.88,2011.14 1009.69,2031.91 849.69,2050.6 2116.71,2052 2515.76,2052.51 1339.24,2059.68 637.37,2066.02 728.64,2072.56 2026.26,2090.97 2424.24,2098.11 919.1,2110.61 1430.76,2115.85 2201.57,2136.86 563.96,2160.95 804.24,2161.65 2538.54,2170.32 2111.11,2175.83 1339.24,2179.68 678.51,2181.59 2453.33,2214.53 1058,2222.3 1858,2222.3 895.76,2228.32 2278.51,2228.94 1430.76,2235.85 2193.78,2262.81 606.62,2277.67 804.24,2281.65 2563.63,2287.67 1346.99,2299.43 1493.09,2338.38 895.76,2348.32 2290.76,2348.32 2199.24,2382.68 1419.97,2394.68 804.24,2401.65 558,2422.3 1158,2422.3 1958,2422.3 2558,2422.3 1575.42,2425.69 895.76,2468.32 2290.76,2468.32 1502.53,2481.77 2186.85,2502.04 1493.47,2601.43 58,2622.3 258,2622.3 658,2622.3 1058,2622.3 1258,2622.3 1858,2622.3 2058,2622.3 2458,2622.3 558,2822.3 758,2822.3 958,2822.3 1158,2822.3 1358,2822.3 1758,2822.3 1958,2822.3 2558,2822.3
NetC1_1: C1.1 J1.1 L1.1
NetC6_1: C6.1 J4.1 R5.1 R10.2 R17.1 | length 408.5
  L1-TOP w10: R10.2@850,2591.5 J4.1@850,2974.17 J4.1@850,3000
NetC7_1: C7.1 J5.1 R6.1 R12.2 R18.1 | length 398.5
  L1-TOP w10: R12.2@2596.5,870 J5.1@2974.17,870 J5.1@2995,870
NetC8_1: C8.1 J6.1 R7.1 R14.2 R19.1 | length 415.6
  L1-TOP w10: J6.1@100,2225 J6.1@125.83,2225 508.5,2225 R14.2@513.5,2220
NetC9_1: C9.1 J7.1 R8.1 R16.2 R20.1 | length 415.6
  L1-TOP w10: J7.1@100,875 J7.1@125.83,875 508.5,875 R16.2@513.5,870
NetC10_1: C10.1 J8.1 R21.1 R26.2 R33.1 | length 410.6
  L1-TOP w10: R26.2@2245,2591.5 2250,2596.5 J8.1@2250,2974.17 J8.1@2250,3000
NetC11_1: C11.1 J9.1 R22.1 R28.2 R34.1 | length 405.6
  L1-TOP w10: R28.2@2596.5,2230 2601.5,2225 J9.1@2974.17,2225 J9.1@3000,2225
NetC12_1: C12.1 J10.1 R23.1 R30.2 R35.1 | length 408.5
  L1-TOP w10: J10.1@2025,100 J10.1@2025,125.83 R30.2@2025,508.5
NetC13_1: C13.1 J11.1 R24.1 R32.2 R36.1 | length 410.2
  L1-TOP w10: R32.2@1074.45,510 1074.45,100.55 J11.1@1075,100
NetJ2_1: J2.1 R2.1 | length 218.5
  L1-TOP w10: R2.1@1550,2781.5 J2.1@1550,2974.17 J2.1@1550,3000
NetJ3_2: J3.2 R4.2 | length 96.5
  L1-TOP w12: R4.2@1611.5,2000 1615,2003.5 J3.2@1615,2095
NetR9_2: R9.2 R10.1 | length 875.1
  L1-TOP w10: R10.1@850,2528.5 850,2156.42 ccw(c950,2156.42) 879.29,2085.71 935.82,2029.18 ccw(c1078.7,2172.06) 1078.7,1970 1094.64,1970 cw(c1094.64,1884.64) 1154.96,1945.04 cw(c1094.64,1884.64) 1155,1945 R9.2@1227.73,1872.27
NetR11_2: R11.2 R12.1 | length 845.1
  L1-TOP w10: R11.2@2056.5,1460 2084.57,1460 cw(c2084.57,1217.55) 2256.01,1388.99 2449.1,1195.9 cw(c2398.65,1145.45) 2470,1145.45 2470,974.93 ccw(c2570,974.93) 2499.29,904.21 R12.1@2533.5,870
NetR13_2: R13.2 R14.1 | length 781.3
  L1-TOP w10: R14.1@576.5,2220 637.98,2158.51 cw(c524.48,2045.01) 685,2045.01 685,2020.42 ccw(c830.87,2020.42) 727.72,1917.28 995,1650 ccw(c1019.14,1674.14) 1019.14,1640 R13.2@1043.5,1640
NetR15_2: R15.2 R16.1 | length 860.7
  L1-TOP w10: R16.1@576.5,870 619.5,913 ccw(c594.13,938.36) 630,938.36 630,1186.96 cw(c661.49,1186.96) 639.22,1209.22 860.22,1430.22 cw(c883.84,1406.6) 883.84,1440 R15.2@1043.5,1440
NetR25_2: R25.2 R26.1 | length 806.3
  L1-TOP w10: R25.2@1872.27,1872.27 2215.71,2215.71 ccw(c2145,2286.42) 2245,2286.42 R26.1@2245,2528.5
NetR27_2: R27.2 R28.1 | length 848.2
  L1-TOP w10: R27.2@2056.5,1665 2199.39,1665 ccw(c2199.39,1690.61) 2217.5,1672.5 2463.48,1918.48 ccw(c2447.73,1934.22) 2470,1934.22 2470,2145.04 cw(c2521.8,2145.04) 2485.17,2181.67 R28.1@2533.5,2230
NetR29_2: R29.2 R30.1 | length 839.1
  L1-TOP w10: R29.2@1872.27,1227.73 1925,1175 ccw(c1961.21,1211.21) 1961.21,1160 1990,1160 cw(c1990,1063.43) 2058.28,1131.72 2063.79,1126.21 cw(c1867.74,930.15) 2145,930.15 2145,866.55 ; R30.1@2025,571.5 2025,615 cw(c2109.5,615) 2049.75,674.75 2072.58,697.58 ccw(c1897.74,872.42) 2144.93,866.55
NetR31_2: R31.2 R32.1 | length 741.8
  L1-TOP w10: R32.1@1074.45,572.99 1074.45,932.19 ccw(c1042.19,932.19) 1065,955 cw(c1089.14,979.14) 1055,979.14 1055,1004.51 cw(c1273.47,1004.51) 1118.99,1158.99 1124.39,1164.39 cw(c1150,1138.79) 1150,1175 1153.79,1175 ccw(c1153.79,1226.21) 1189.99,1189.99 R31.2@1227.73,1227.73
